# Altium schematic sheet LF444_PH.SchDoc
size A3; SheetNumber: 0; SheetTotal: 0
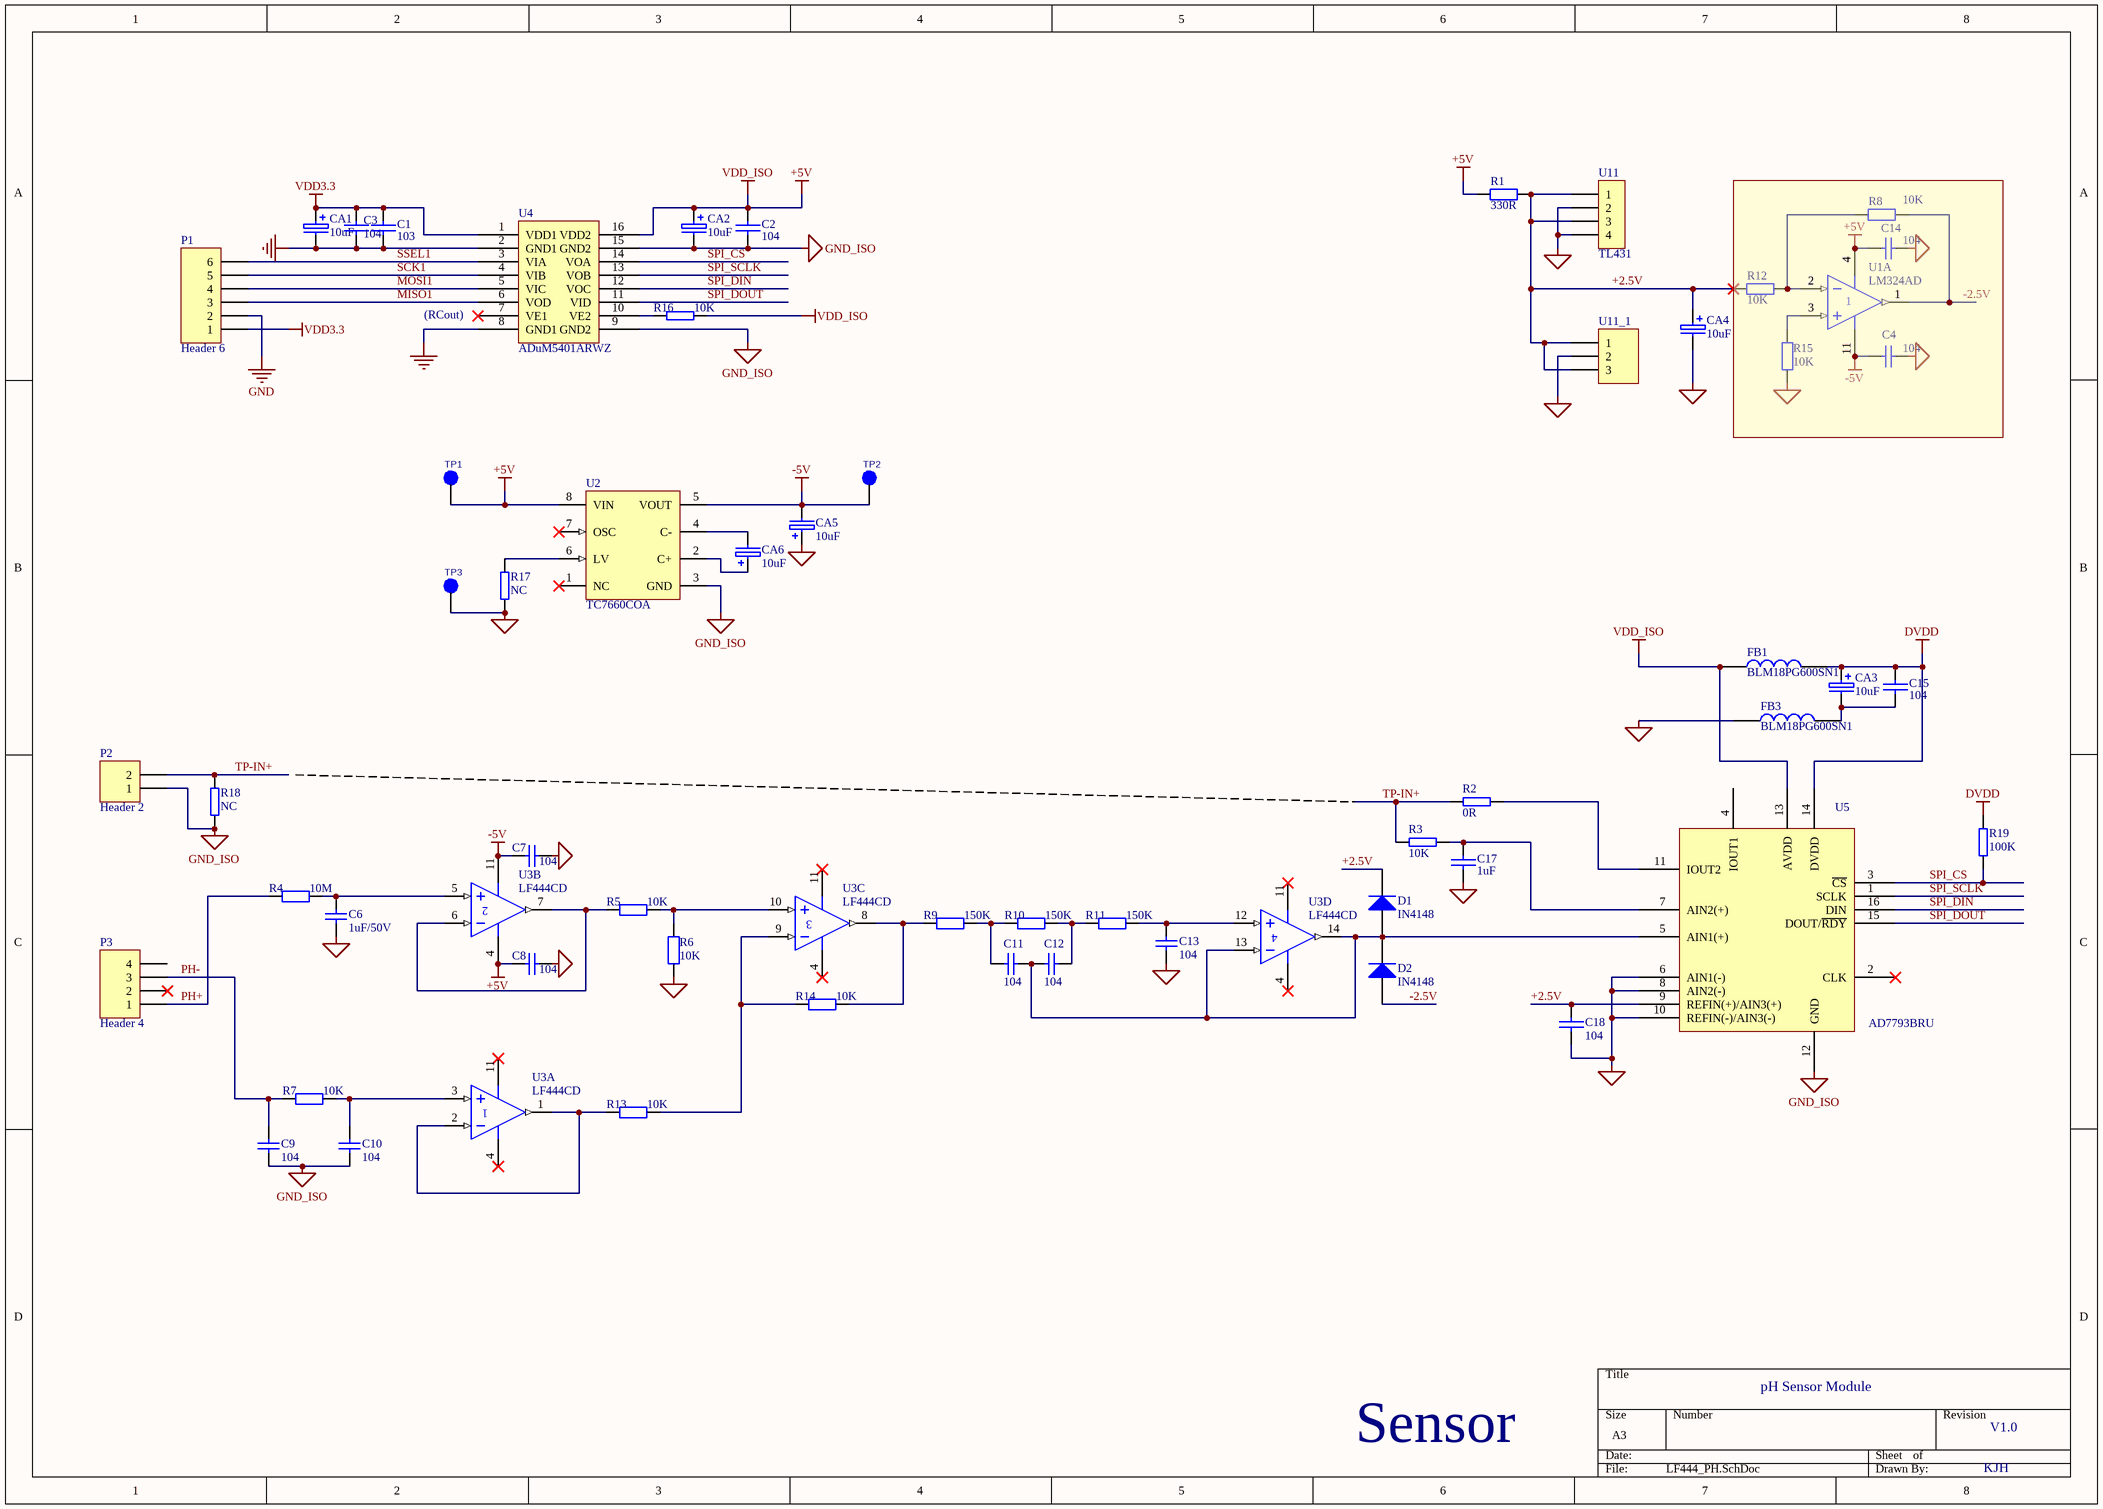
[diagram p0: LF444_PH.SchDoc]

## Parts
C1  103  [SM0603]
C2  104  [SM0603]
C3  104  [SM0603]
C4  104  [SM0603]
C6  1uF/50V  [SM0805]
C7  104  [SM0603]
C8  104  [SM0603]
C9  104  [SM0603]
C10  104  [SM0603]
C11  104  [SM0603]
C12  104  [SM0603]
C13  104  [SM0603]
C14  104  [SM0603]
C15  104  [SM0603]
C17  1uF  [SM0603]
C18  104  [SM0603]
CA1  10uF  [SM1206]
CA2  10uF  [SM1206]
CA3  10uF  [SM1206]
CA4  10uF  [SM1206]
CA5  10uF  [SM1206]
CA6  10uF  [SM1206]
D1  IN4148  [1206D]
D2  IN4148  [1206D]
FB1  BLM18PG600SN1  [SM0603]
FB3  BLM18PG600SN1  [SM0603]
P1  Header 6  [HDR1X6]
P2  Header 2  [HDR1X2]
P3  Header 4  [HDR1X4]
R1  330R  [SM0603]
R2  0R  [SM0603]
R3  10K  [SM0603]
R4  10M  [SM0603]
R5  10K  [SM0603]
R6  10K  [SM0603]
R7  10K  [SM0603]
R8  10K  [SM0603]
R9  150K  [SM0603]
R10  150K  [SM0603]
R11  150K  [SM0603]
R12  10K  [SM0603]
R13  10K  [SM0603]
R14  10K  [SM0603]
R15  10K  [SM0603]
R16  10K  [SM0603]
R17  NC  [SM0603]
R18  NC  [SM0603]
R19  100K  [SM0603]
TP1  +5V  [test point]  (value not drawn)
TP2  -5V  [test point]  (value not drawn)
TP3  GND  [test point]  (value not drawn)
U1  LM324AD  [751A-02_N]  (part A of 4)
U2  TC7660COA  [SOIC-OA8_N]
U3  LF444CD  [751A-03_N]  (parts A,B,C,D of 4)
U4  ADuM5401ARWZ  [ADUM1401]
U5  AD7793BRU  [AD7793]
U11  TL431  [7805 - DUPLICATE]
U11_1  TL431  [HDR1X3]  (value not drawn)

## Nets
+5V: C2.1 C8.2 C14.1 CA2.1 FB1.1 R1.2 R16.2 TP1.1 U1.4(V+) U2.8(VIN) U3.4(V+) U4.16(VDD2) U5.13(AVDD)  [also labelled VDD_ISO]
-5V: C4.1 C7.2 CA5.2 TP2.1 U1.11(V-) U2.5(VOUT) U3.11(V-)
DVDD: C15.1 CA3.1 FB1.2 R19.2 U5.14(DVDD)
GND: C1.2 C3.1 CA1.2 P1.2 U4.2(GND1) U4.8(GND1)
GND_ISO: C2.2 C4.2 C6.1 C7.1 C8.1 C9.1 C10.1 C13.1 C14.2 C17.2 C18.2 CA2.2 CA4.2 CA5.1 FB3.1 P2.1 R6.1 R15.2 R17.1 R18.1 TP3.1 U2.3(GND) U4.9(GND2) U4.15(GND2) U5.6(AIN1(-)) U5.8(AIN2(-)) U5.10(REFIN(-)/AIN3(-)) U5.12(GND) U11.2 U11.4 U11_1.2
VDD3.3: C1.1 C3.2 CA1.1 P1.1 U4.1(VDD1)
+2.5V: C18.1 CA4.1 D1.2(K) R1.1 R12.1 U5.9(REFIN(+)/AIN3(+)) U11.1 U11.3 U11_1.1 U11_1.3
-2.5V: D2.1(A) R8.2 U1.1(OUT)
MISO1: P1.3 U4.6(VOD)
MOSI1: P1.4 U4.5(VIC)
PH+: P3.1 R4.1
PH-: C9.2 P3.3 R7.1
SCK1: P1.5 U4.4(VIB)
SPI_CS: R19.1 U4.14(VOA) U5.3(~{CS})
SPI_DIN: U4.12(VOC) U5.16(DIN)
SPI_DOUT: U4.11(VID) U5.15(DOUT/~{RDY})
SPI_SCLK: U4.13(VOB) U5.1(SCLK)
SSEL1: P1.6 U4.3(VIA)
TP-IN+: P2.2 R2.1 R3.1 R18.2
NetC6_2: C6.2 R4.2 U3.5(IN+)
NetC10_2: C10.2 R7.2 U3.3(IN+)
NetC11_1: C11.1 C12.2 D1.1(A) D2.2(K) U3.13(IN-) U3.14(OUT) U5.5(AIN1(+))
NetC11_2: C11.2 R9.2 R10.1
NetC12_1: C12.1 R10.2 R11.1
NetC13_2: C13.2 R11.2 U3.12(IN+)
NetC15_2: C15.2 CA3.2 FB3.2
NetC17_1: C17.1 R3.2 U5.7(AIN2(+))
NetCA6_1: CA6.1 U2.2(C+)
NetCA6_2: CA6.2 U2.4(C-)
NetR2_2: R2.2 U5.11(IOUT2)
NetR5_1: R5.1 U3.6(IN-) U3.7(OUT)
NetR5_2: R5.2 R6.2 U3.10(IN+)
NetR8_1: R8.1 R12.2 U1.2(IN-)
NetR9_1: R9.1 R14.2 U3.8(OUT)
NetR13_1: R13.1 U3.1(OUT) U3.2(IN-)
NetR13_2: R13.2 R14.1 U3.9(IN-)
NetR15_1: R15.1 U1.3(IN+)
NetR16_1: R16.1 U4.10(VE2)
NetR17_2: R17.2 U2.6(LV)

Not connected (* = marked no-connect by the designer): P3 2* 4; U2 1(NC)* 7(OSC)*; U4 7(VE1)*; U5 2(CLK)* 4(IOUT1)

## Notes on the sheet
- (near U4) (RCout)
- pH Sensor Module
- Sensor
- V1.0
- KJH

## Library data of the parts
C1-C3 C15 C17 = CA: 电容
C4 C7-C14 = Cap: C?
C6 = Î: C
C18 = CAP: Capacitor
CA1-CA6 = CAPE: 极性电容
D1 D2 = 二极管: DIODE
FB1 FB3 = INDUCTOR
P1 = Header 6: Header, 6-Pin
P2 = Header 2: Header, 2-Pin
P3 = Header 4: Header, 4-Pin
R1 R4-R15 = Res: R?
R2 R3 R16-R19 = RE: 电阻
TP1-TP3 = PAD
U1 = LM324AD: Quad Low-Power Operational Amplifier
U2 = TC7660COA: Charge Pump DC-to-DC Voltage Converter, 8-Pin SOIC 150mil, Commercial Temperature
U3 = LF444CD: Low Power JFET Input Operational Amplifier
U4 = ADUM1401: 1Mbps Data Rate, 100ns Propagation delay
U5 = AD7793
U11 = CON4: Connector
U11_1 = Header 3: Header, 3-Pin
